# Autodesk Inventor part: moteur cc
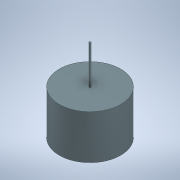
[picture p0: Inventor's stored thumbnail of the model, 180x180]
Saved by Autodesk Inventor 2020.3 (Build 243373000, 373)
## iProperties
Created: 2020-09
Part Number: moteur cc
Material: Acier
Document SubType Name: Modeling
Designer: ficho
Density: 7.85 g/cm^3
Appearance: Plomb
Author: ficho
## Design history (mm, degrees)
sketch "Esquisse1"
  geometry: L1 (0, 0)-(16, 0); L2 (16, 0)-(16, 23); L3 (16, 23)-(0, 23); L4 (0, 23)-(0, 0); L5 (0, 23)-(0.5, 23); L6 (0.5, 23)-(0.5, 43); L7 (0.5, 43)-(0, 43); L8 (0, 43)-(0, 23); 1 further point
  constraints: 16 end point, 4 parallel, 2 horizontal, 2 perpendicular
  dimensions: "d0" = 16 distance of L3.end L2.end; "d1" = 23 distance of L2.end L1.end; "d2" = 0.5 distance of L7.end L6.end; "d3" = 20 distance of L6.end L5.end
revolve "Révolution1" sketch "Esquisse1" stored, may be unused: angle "d4" = 90 deg
node "Solide1"
